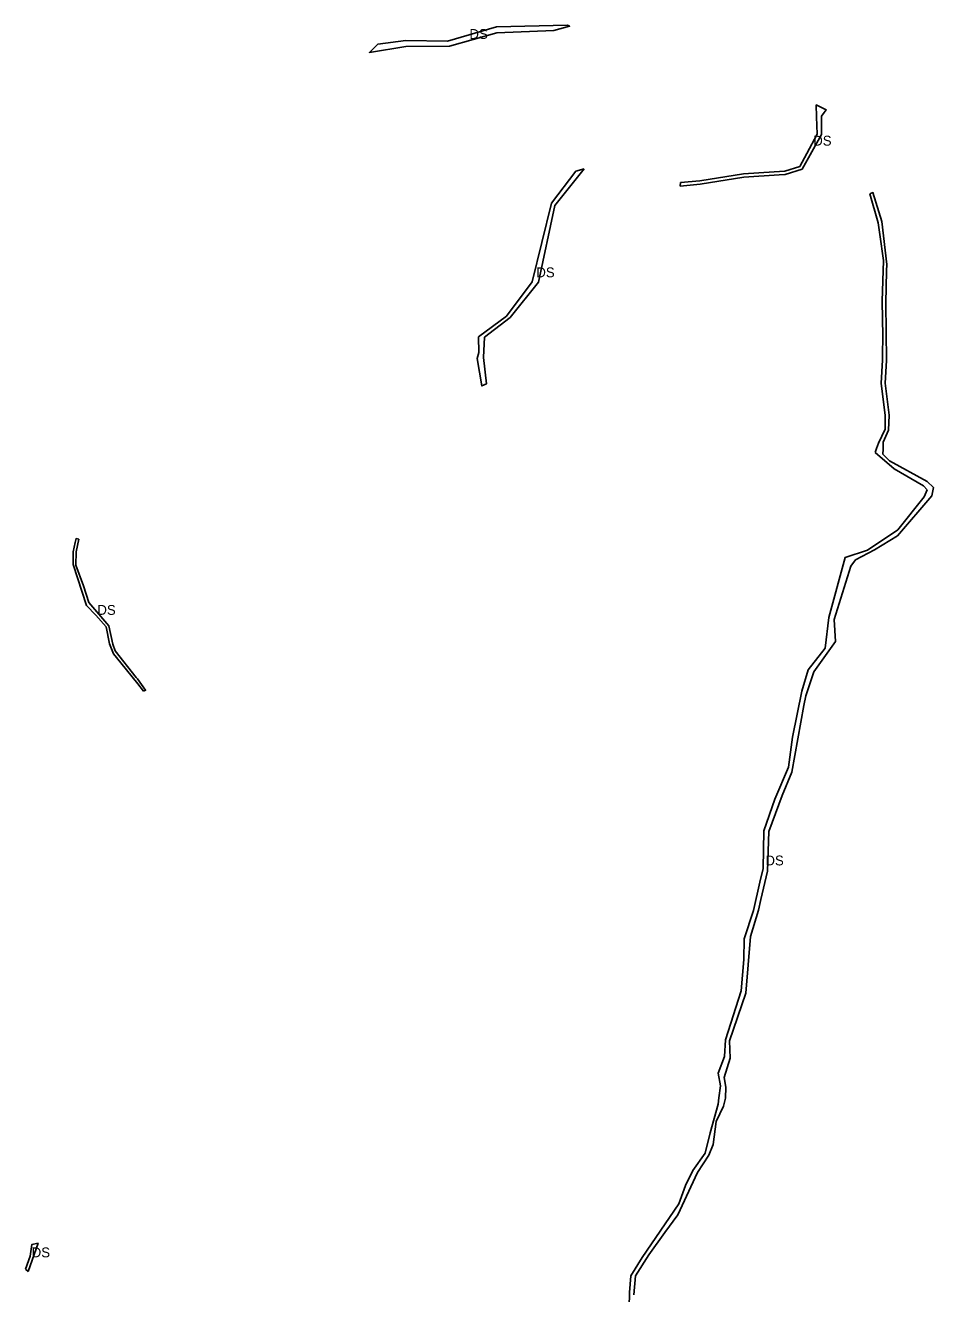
# Model space of a CAD drawing. Extents: x -477304 to -465641, y -1159113 to -1149285.
# Drawn here: x -475774 to -474946, y -1150441 to -1149285 of the extents above; entities that cross this region are included whole.
import ezdxf

# ---------------------------------------------------------------- set-up
doc = ezdxf.new("R2010")
doc.units = 0
doc.layers.add('35', color=7, linetype='Continuous')

msp = doc.modelspace()

# ---------------------------------------------------------------- linework, layer by layer
at = {"layer": '35'}
for p, q in [((-475279.6, -1149284.8), (-475344.4, -1149286.3)), ((-475387.1, -1149303.7), (-475344, -1149291.5)), ((-475426.9, -1149298.5), (-475452.6, -1149302.1)), ((-475427.1, -1149304), (-475387.1, -1149303.7)), ((-475047.9, -1149367.7), (-475045.5, -1149364.4)), ((-475291, -1149449.2), (-475264.3, -1149415.6)), ((-475264.3, -1149415.6), (-475272.1, -1149417.7)), ((-475091.1, -1149418.3), (-475119.1, -1149420.2)), ((-475081.2, -1149417.7), (-475091.1, -1149418.3)), ((-475086.4, -1149421.1), (-475081, -1149420.8)), ((-475081, -1149420.8), (-475065.6, -1149416)), ((-475003.8, -1149438.4), (-474996.1, -1149464.9)), ((-475306.1, -1149519), (-475291, -1149449.2)), ((-474996.1, -1149464.9), (-474994.6, -1149475.6)), ((-474994.6, -1149475.6), (-474991.3, -1149499.3)), ((-474988.6, -1149508.8), (-474988.3, -1149502.9)), ((-474989.3, -1149538.3), (-474988.6, -1149508.8)), ((-475311.9, -1149518.8), (-475335.3, -1149549.9)), ((-474988.5, -1149590.4), (-474989.3, -1149538.3)), ((-475335.3, -1149549.9), (-475360.8, -1149568.8)), ((-474991.9, -1149568.4), (-474992.2, -1149585.4)), ((-474992.2, -1149585.4), (-474992.3, -1149590.3)), ((-474989.7, -1149640.7), (-474989.8, -1149653.1)), ((-474986.8, -1149654.1), (-474986, -1149640.4)), ((-474991.6, -1149664.9), (-474986.8, -1149654.1)), ((-474991.7, -1149671.4), (-474991.6, -1149664.9)), ((-474997.7, -1149670.7), (-474998.9, -1149674.5)), ((-474991.8, -1149675.9), (-474991.7, -1149671.4)), ((-474951.6, -1149708.3), (-474954.3, -1149714.9)), ((-474947.2, -1149713.9), (-474945.6, -1149706.2)), ((-474954.3, -1149714.9), (-474978.2, -1149744.8)), ((-475728.7, -1149756.3), (-475730.5, -1149765)), ((-475730.5, -1149765), (-475730.6, -1149776.6)), ((-475017, -1149772.1), (-474999.6, -1149763.2)), ((-475730.6, -1149776.6), (-475718.2, -1149814)), ((-475718.2, -1149814), (-475709.8, -1149822.8)), ((-475698, -1149832.4), (-475716.2, -1149811.2)), ((-475697.3, -1149848.9), (-475693.8, -1149858)), ((-475693.8, -1149858), (-475687, -1149866.2)), ((-475672.9, -1149879.5), (-475692.2, -1149855.2)), ((-475687, -1149866.2), (-475671.6, -1149885.3)), ((-475671.9, -1149880.8), (-475672.9, -1149879.5)), ((-475671.6, -1149885.3), (-475666.2, -1149891.9)), ((-475097, -1150056), (-475095.9, -1150020)), ((-475103.1, -1150081.9), (-475097, -1150056)), ((-475105.3, -1150091.8), (-475103.1, -1150081.9)), ((-475131.9, -1150211), (-475116.9, -1150167.4)), ((-475131.3, -1150226.7), (-475131.9, -1150211)), ((-475142, -1150268.7), (-475149.4, -1150294.7)), ((-475146.8, -1150305.5), (-475143.9, -1150284.4)), ((-475771.5, -1150421.2), (-475762.5, -1150395.4)), ((-475217.5, -1150425.1), (-475205.4, -1150405.9)), ((-475769.7, -1150407.2), (-475774.1, -1150419)), ((-475774.1, -1150419), (-475771.5, -1150421.2)), ((-475219, -1150442.5), (-475217.5, -1150425.1)), ((-475223.1, -1150440.3), (-475224.1, -1150488.4))]:
    msp.add_line(p, q, dxfattribs=at)
for points in [[(-475344, -1149291.5), (-475291.9, -1149289.4), (-475277.7, -1149285.7), (-475279.6, -1149284.8)], [(-475344.4, -1149286.3), (-475388.9, -1149299.3), (-475426.9, -1149298.5)], [(-475452.6, -1149302.1), (-475460.3, -1149309.5), (-475427.1, -1149304)], [(-475045.5, -1149364.4), (-475043.5, -1149361.9), (-475052.7, -1149357.4), (-475052.3, -1149368.1), (-475051.7, -1149384.2), (-475061.3, -1149401.8)], [(-475065.6, -1149416), (-475047.9, -1149384.5), (-475047.9, -1149367.7)], [(-475061.3, -1149401.8), (-475067.7, -1149413.5), (-475081.2, -1149417.7)], [(-475272.1, -1149417.7), (-475294.3, -1149447.1), (-475311.9, -1149518.8)], [(-475119.1, -1149420.2), (-475158.8, -1149426.7), (-475176.4, -1149428.2), (-475176.9, -1149431.5)], [(-475176.9, -1149431.5), (-475158.6, -1149429.7), (-475118.6, -1149423.2), (-475086.4, -1149421.1)], [(-474988.3, -1149502.9), (-474992.9, -1149463.6), (-475001, -1149437.4), (-475003.8, -1149438.4)], [(-474991.3, -1149499.3), (-474992.6, -1149536.3), (-474991.9, -1149568.4)], [(-475353.4, -1149611.8), (-475356.2, -1149587.8), (-475355.2, -1149569.2), (-475332, -1149551.1), (-475306.1, -1149519)], [(-475360.8, -1149568.8), (-475360.4, -1149583.3), (-475362, -1149588.7)], [(-475362, -1149588.7), (-475357.8, -1149613.7), (-475353.4, -1149611.8)], [(-474992.3, -1149590.3), (-474993.3, -1149611), (-474989.7, -1149640.7)], [(-474986, -1149640.4), (-474989.7, -1149611.1), (-474988.5, -1149590.4)], [(-474989.8, -1149653.1), (-474995.9, -1149665.8), (-474997.7, -1149670.7)], [(-474998.9, -1149674.5), (-474981.7, -1149689.1), (-474954.7, -1149704.8), (-474951.6, -1149708.3)], [(-474945.6, -1149706.2), (-474951.4, -1149700.8), (-474985.8, -1149681.9), (-474991.8, -1149675.9)], [(-474999.6, -1149763.2), (-474978.6, -1149750.2), (-474947.2, -1149713.9)], [(-474978.2, -1149744.8), (-475005.9, -1149763.5), (-475026.2, -1149770), (-475041.3, -1149824.7), (-475044.6, -1149852.8), (-475059.9, -1149872.6)], [(-475716.2, -1149811.2), (-475721.2, -1149795.8), (-475727.9, -1149777.1), (-475727.6, -1149765), (-475725.4, -1149753.5), (-475727.8, -1149752.9), (-475728.7, -1149756.3)], [(-475035, -1149846.6), (-475036.2, -1149826.5), (-475021.2, -1149777.9), (-475017, -1149772.1)], [(-475709.8, -1149822.8), (-475700.3, -1149833.4), (-475697.3, -1149848.9)], [(-475692.2, -1149855.2), (-475694.3, -1149849.2), (-475698, -1149832.4)], [(-475074.9, -1149965.9), (-475064, -1149905.2), (-475062.3, -1149896.4), (-475054.8, -1149874.3), (-475035, -1149846.6)], [(-475059.9, -1149872.6), (-475065.7, -1149892), (-475074.3, -1149933.9), (-475078.1, -1149961.4)], [(-475666.2, -1149891.9), (-475664.4, -1149891.1), (-475671.9, -1149880.8)], [(-475078.1, -1149961.4), (-475090.3, -1149990.4), (-475100.4, -1150019.4), (-475101.2, -1150053.6), (-475104, -1150066.2), (-475110, -1150092)], [(-475095.9, -1150020), (-475083.9, -1149987.2), (-475074.9, -1149965.9)], [(-475110, -1150092), (-475118.5, -1150117.8), (-475118.7, -1150136.8)], [(-475116.9, -1150167.4), (-475112.6, -1150115.6), (-475105.3, -1150091.8)], [(-475118.7, -1150136.8), (-475121.1, -1150165.3), (-475135.3, -1150210), (-475136.3, -1150225.2)], [(-475136.3, -1150225.2), (-475142.1, -1150240.4), (-475140, -1150251.9)], [(-475135.5, -1150263), (-475135.2, -1150253.1), (-475136.7, -1150244.4), (-475131.3, -1150226.7)], [(-475140, -1150251.9), (-475141.6, -1150262.9), (-475142, -1150268.7)], [(-475143.9, -1150284.4), (-475137.3, -1150270.4), (-475135.5, -1150263)], [(-475149.4, -1150294.7), (-475154.1, -1150313.4), (-475165.3, -1150329)], [(-475179, -1150369.4), (-475161, -1150330.8), (-475150.5, -1150315.2), (-475146.8, -1150305.5)], [(-475165.3, -1150329), (-475172, -1150342.9), (-475178, -1150359.6), (-475211.6, -1150408.4)], [(-475205.4, -1150405.9), (-475190.7, -1150385.6), (-475179, -1150369.4)], [(-475762.5, -1150395.4), (-475768.3, -1150396.6), (-475769.7, -1150407.2)], [(-475211.6, -1150408.4), (-475221.7, -1150425.2), (-475223.1, -1150440.3)]]:
    msp.add_lwpolyline(points, dxfattribs=at)

# ---------------------------------------------------------------- texts
for p in [(-475369, -1149297.2), (-475055.4, -1149394.5), (-475308, -1149514.6), (-475708.4, -1149822.4), (-475099, -1150050.9), (-475768.3, -1150408.3)]:
    msp.add_text('DS', height=9, dxfattribs=at).set_placement(p)

doc.saveas('drawing.dxf')
